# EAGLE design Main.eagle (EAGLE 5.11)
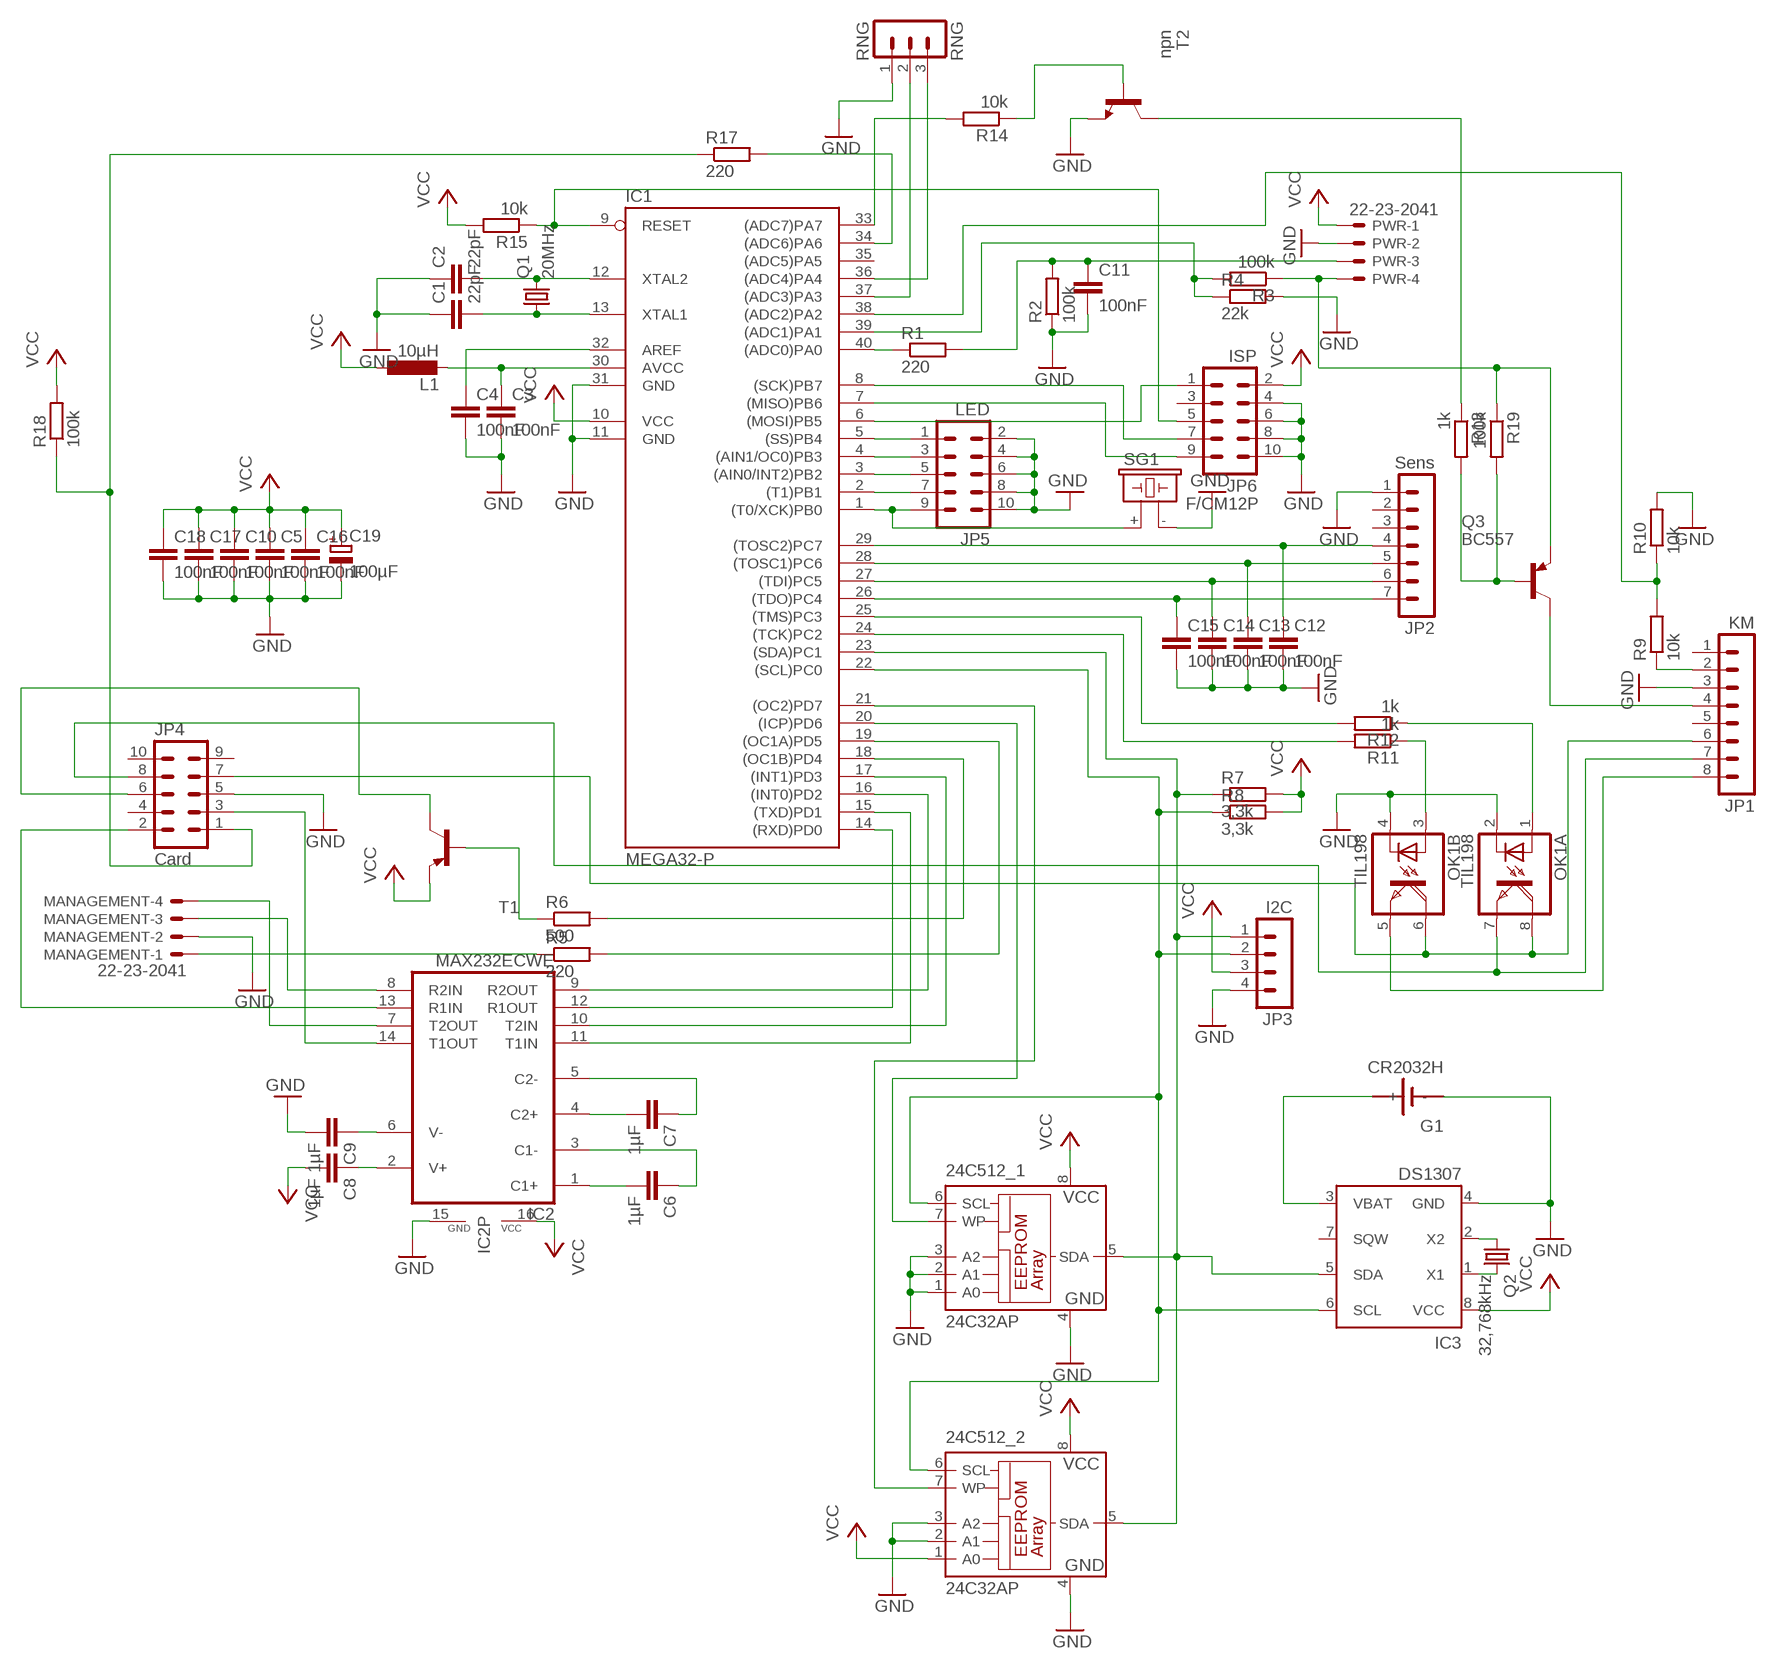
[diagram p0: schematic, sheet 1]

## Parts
24C512_1  24C32AP  [DIL8]
24C512_2  24C32AP  [DIL8]
C1  22pF  C-EUC0603  [C0603]
C2  22pF  C-EUC0603  [C0603]
C3  100nF  C-EUC0603  [C0603]
C4  100nF  C-EUC0603  [C0603]
C5  100nF  C-EUC0603  [C0603]
C6  1µF  C-EUC0603  [C0603]
C7  1µF  C-EUC0603  [C0603]
C8  1µF  C-EUC0603  [C0603]
C9  1µF  C-EUC0603  [C0603]
C10  100nF  C-EUC0603  [C0603]
C11  100nF  C-EUC0603  [C0603]
C12  100nF  C-EUC0603  [C0603]
C13  100nF  C-EUC0603  [C0603]
C14  100nF  C-EUC0603  [C0603]
C15  100nF  C-EUC0603  [C0603]
C16  100nF  C-EUC0603  [C0603]
C17  100nF  C-EUC0603  [C0603]
C18  100nF  C-EUC0603  [C0603]
C19  100µF  CPOL-EUE2.5-7  [E2,5-7]
G1  CR2032H  SN2032  [SN2032]
IC1  MEGA32-P  [DIL40]
IC2  MAX232ECWE  [SO16L]
IC3  DS1307  [DIL08]
JP1  KM  MA08-1  [MA08-1]
JP2  Sens  MA07-1  [MA07-1]
JP3  I2C  MA04-1  [MA04-1]
JP4  Card  MA05-2  [MA05-2]
JP5  LED  ML10  [ML10]
JP6  ISP  ML10  [ML10]
L1  10µH  L-EU0207/7  [0207/7]
MANAGEMENT  22-23-2041  [22-23-2041]
OK1  TIL198  [DIL08]
PWR  22-23-2041  [22-23-2041]
Q1  20MHz  CRYSTALHC49S  [HC49/S]
Q2  32,768kHz  CRYSTALTC26H  [TC26H]
Q3  BC557  [TO92-EBC]
R1  220  R-EU_R0603  [R0603]
R2  100k  R-EU_R0603  [R0603]
R3  100k  R-EU_R0603  [R0603]
R4  22k  R-EU_R0603  [R0603]
R5  220  R-EU_R0603  [R0603]
R6  500  R-EU_R0603  [R0603]
R7  3,3k  R-EU_R0603  [R0603]
R8  3,3k  R-EU_R0603  [R0603]
R9  10k  R-EU_R0603  [R0603]
R10  10k  R-EU_R0603  [R0603]
R11  1k  R-EU_R0603  [R0603]
R12  1k  R-EU_R0603  [R0603]
R13  1k  R-EU_R0603  [R0603]
R14  10k  R-EU_R0603  [R0603]
R15  10k  R-EU_R0603  [R0603]
R17  220  R-EU_R0603  [R0603]
R18  100k  R-EU_R0603  [R0603]
R19  100k  R-EU_R0603  [R0603]
RNG  RNG  MA03-1  [MA03-1]
SG1  F/CM12P  [F/CM12P]
T1  BC557  [TO92-EBC]
T2  npn  BC167-NPN-TO92-ECB  [TO92-ECB]

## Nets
AVCC: C3.1 IC1.30(AVCC) L1.2
GND: 24C512_1.1(A0) 24C512_1.2(A1) 24C512_1.3(A2) 24C512_1.4(GND) 24C512_2.2(A1) 24C512_2.3(A2) 24C512_2.4(GND) C1.1 C2.1 C3.2 C4.2 C5.2 C9.2 C10.2 C11.2 C12.2 C13.2 C14.2 C15.2 C16.2 C17.2 C18.2 C19.- G1.- IC1.11(GND) IC1.31(GND) IC2.15(GND) IC3.4(GND) JP1.3 JP2.1 JP3.4 JP4.5 JP5.2 JP5.4 JP5.6 JP5.8 JP5.10 JP6.4 JP6.6 JP6.8 JP6.10 MANAGEMENT.2 OK1.2(A:C) OK1.4(B:C) PWR.2 R2.1 R4.2 R10.2 RNG.1 SG1.- T2.E
N$2: C4.1 IC1.32(AREF)
N$3: IC1.8((SCK)PB7) JP6.7
N$4: IC1.7((MISO)PB6) JP6.9
N$5: C6.2 IC2.1(C1+)
N$6: C6.1 IC2.3(C1-)
N$7: C1.2 IC1.13(XTAL1) Q1.1
N$8: C2.2 IC1.12(XTAL2) Q1.2
N$9: C7.2 IC2.4(C2+)
N$10: C7.1 IC2.5(C2-)
N$11: C9.1 IC2.6(V-)
N$12: C8.1 IC2.2(V+)
N$13: IC1.6((MOSI)PB5) JP6.1
N$14: IC1.9(RESET) JP6.5 R15.1
N$15: IC1.14((RXD)PD0) IC2.12(R1OUT)
N$16: IC1.15((TXD)PD1) IC2.11(T1IN)
N$17: IC1.16((INT0)PD2) IC2.9(R2OUT)
N$18: IC1.17((INT1)PD3) IC2.10(T2IN)
N$19: IC1.1((T0/XCK)PB0) JP5.9 SG1.+
N$20: IC1.2((T1)PB1) JP5.7
N$21: IC1.3((AIN0/INT2)PB2) JP5.5
N$22: IC1.4((AIN1/OC0)PB3) JP5.3
N$23: IC1.5((SS)PB4) JP5.1
N$25: IC2.7(T2OUT) MANAGEMENT.4
N$26: C11.1 PWR.3 R1.2 R2.2
N$27: IC1.40((ADC0)PA0) R1.1
N$28: C12.1 IC1.29((TOSC2)PC7) JP2.4
N$29: IC1.39((ADC1)PA1) R3.2 R4.1
N$30: C13.1 IC1.28((TOSC1)PC6) JP2.5
N$31: C14.1 IC1.27((TDI)PC5) JP2.6
N$32: C15.1 IC1.26((TDO)PC4) JP2.7
N$33: IC2.8(R2IN) MANAGEMENT.3
N$34: R6.1 T1.B
N$35: IC1.19((OC1A)PD5) R5.2
N$36: MANAGEMENT.1 R5.1
N$37: IC1.18((OC1B)PD4) R6.2
N$38: IC2.13(R1IN) JP4.2
N$39: IC2.14(T1OUT) JP4.3
N$40: JP1.6 JP4.7 OK1.6(B:COL) OK1.8(A:COL)
N$41: IC1.34((ADC6)PA6) R17.2
N$42: JP4.6 T1.C
N$43: IC3.2(X2) Q2.1
N$44: IC3.1(X1) Q2.2
N$45: 24C512_1.5(SDA) 24C512_2.5(SDA) IC1.23((SDA)PC1) IC3.5(SDA) JP3.1 R7.1
N$46: IC1.25((TMS)PC3) R12.2
N$47: OK1.3(B:A) R11.1
N$48: OK1.1(A:A) R12.1
N$49: 24C512_1.6(SCL) 24C512_2.6(SCL) IC1.22((SCL)PC0) IC3.6(SCL) JP3.2 R8.1
N$50: 24C512_1.7(WP) IC1.20((ICP)PD6)
N$51: 24C512_2.7(WP) IC1.21((OC2)PD7)
N$52: JP4.1 R17.1 R18.1
N$53: G1.+ IC3.3(VBAT)
N$54: JP1.7 JP4.8 OK1.7(A:EMI)
N$55: JP1.8 OK1.5(B:EMI)
N$56: JP1.4 Q3.C
N$57: IC1.38((ADC2)PA2) R9.2 R10.1
N$58: R13.1 T2.C
N$59: JP1.2 R9.1
N$60: Q3.B R13.2 R19.2
N$61: IC1.24((TCK)PC2) R11.2
N$62: IC1.33((ADC7)PA7) R14.2
N$63: R14.1 T2.B
N$64: PWR.4 Q3.E R3.1 R19.1
N$65: IC1.37((ADC3)PA3) RNG.2
N$66: IC1.36((ADC4)PA4) RNG.3
VCC: 24C512_1.8(VCC) 24C512_2.1(A0) 24C512_2.8(VCC) C5.1 C8.2 C10.1 C16.1 C17.1 C18.1 C19.+ IC1.10(VCC) IC2.16(VCC) IC3.8(VCC) JP3.3 JP6.2 L1.1 PWR.1 R7.2 R8.2 R15.2 R18.2 T1.E
Unconnected: IC1.35((ADC5)PA5) IC3.7(SQW) JP1.1 JP1.5 JP2.2 JP2.3 JP4.4 JP4.9 JP4.10 JP6.3

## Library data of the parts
24C512_1 24C512_2 = microchip:24*: Serial EEPROM I2C; MPN: AT24C32C-PU; OC_FARNELL: 1362652; OC_NEWARK: 50M3325
C1-C18 = rcl:C-EU: CAPACITOR, European symbol
C19 = rcl:CPOL-EU: POLARIZED CAPACITOR, European symbol
G1 = sn2032:SN2032: LI BATTERY
IC1 = atmel:MEGA32-P: MICROCONTROLLER 32 Kbytes FLASH 2 Kbytes SRAM 1 Kbytes EEPROM USART 8-channel 10 bit ADC Source: www.atmel.com .. doc2503.pdf; MPN: ATMEGA32-16PU; OC_FARNELL: 1661729; OC_NEWARK: 51P1794
IC2 = maxim:MAX232ECWE: RS232 TRANSEIVER; MF: MAXIM; MPN: MAX232ECWE+; OC_FARNELL: 9724435; OC_NEWARK: 67K4440
IC3 = ds1307_pcf8583:DS1307: I2C-Bus CLOCK/CALENDAR
JP1 = con-lstb:MA08-1: PIN HEADER; OC_FARNELL: unknown; OC_NEWARK: unknown
JP2 = con-lstb:MA07-1: PIN HEADER; OC_FARNELL: unknown; OC_NEWARK: unknown
JP3 = con-lstb:MA04-1: PIN HEADER; OC_FARNELL: unknown; OC_NEWARK: unknown
JP4 = con-lstb:MA05-2: PIN HEADER; OC_FARNELL: unknown; OC_NEWARK: unknown
JP5 JP6 = con-ml:ML10: HARTING; OC_FARNELL: unknown; OC_NEWARK: unknown
L1 = rcl:L-EU: INDUCTOR, European symbol
MANAGEMENT PWR = con-molex:22-23-2041: .100" (2.54mm) Center Header - 4 Pin; MF: MOLEX; MPN: 22-23-2041; OC_FARNELL: 1462920; OC_NEWARK: 38C0355
OK1 = optocoupler:TIL198: TEXAS INSTRUMENTS OPTO COUPLER; OC_FARNELL: unknown; OC_NEWARK: unknown
Q1 = crystal:CRYSTAL: CRYSTAL; OC_FARNELL: 1667008; OC_NEWARK: unknown
Q2 = crystal:CRYSTAL: CRYSTAL; OC_FARNELL: unknown; OC_NEWARK: unknown
Q3 T1 = transistor-pnp:BC557*: PNP Transistror
R1-R15 R17-R19 = rcl:R-EU_: RESISTOR, European symbol
RNG = con-lstb:MA03-1: PIN HEADER; OC_FARNELL: unknown; OC_NEWARK: unknown
SG1 = buzzer:F/CM12P: BUZZER; OC_FARNELL: unknown; OC_NEWARK: unknown
T2 = transistor:*-NPN-: NPN Transistror BF959 corrected 2008.03.06

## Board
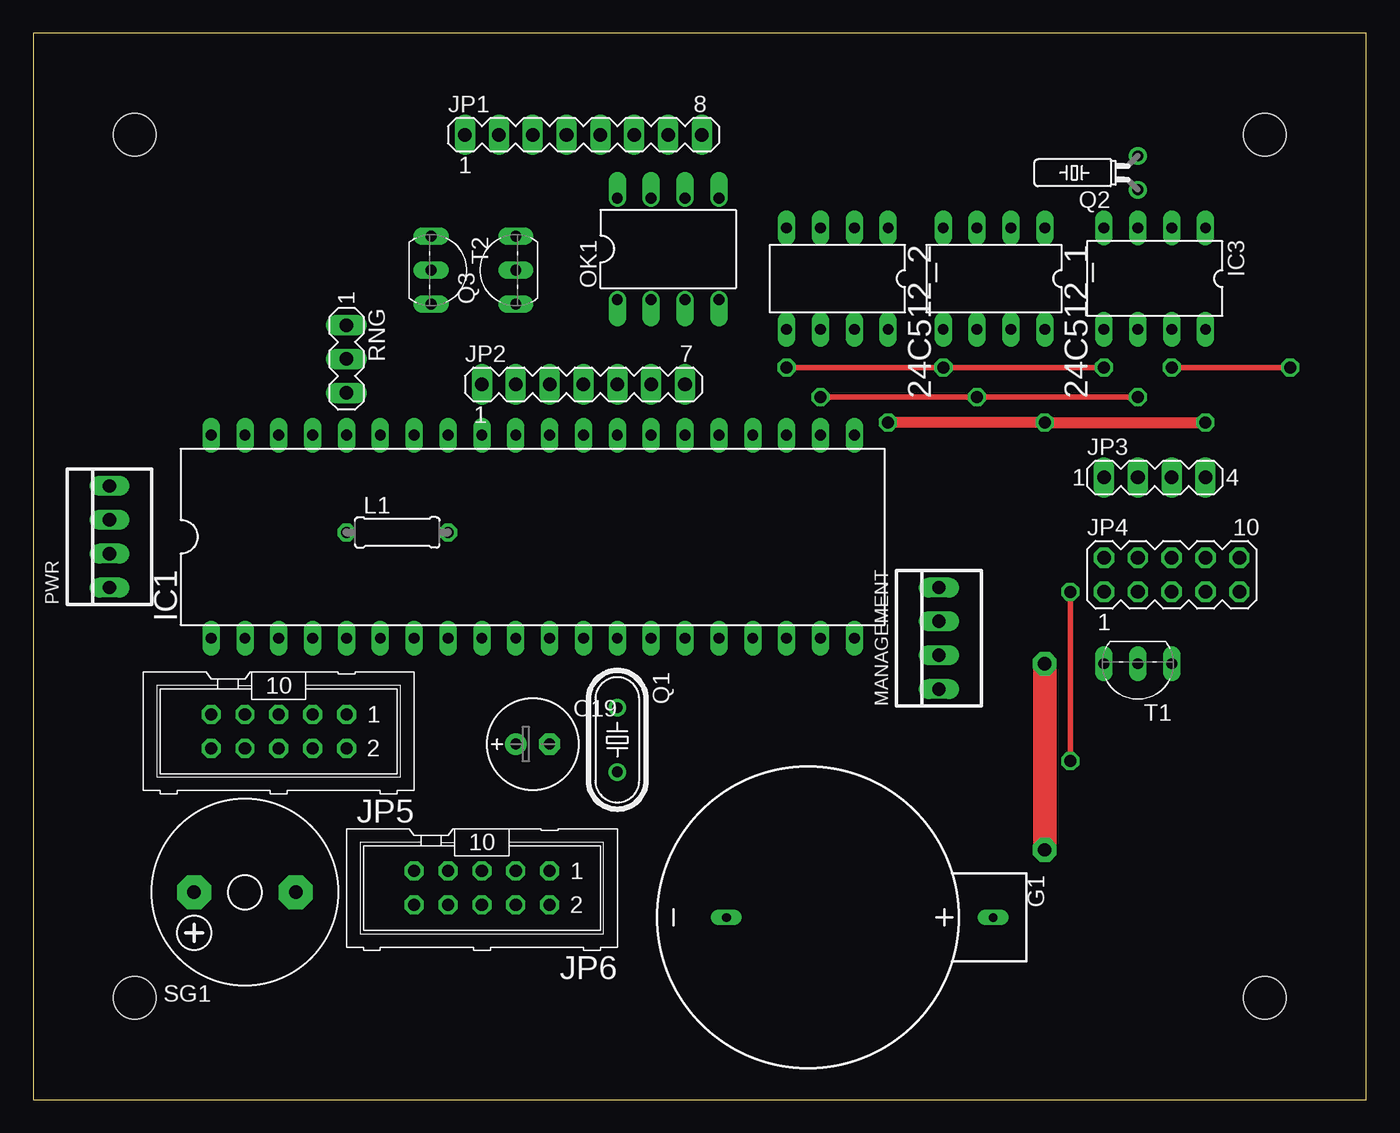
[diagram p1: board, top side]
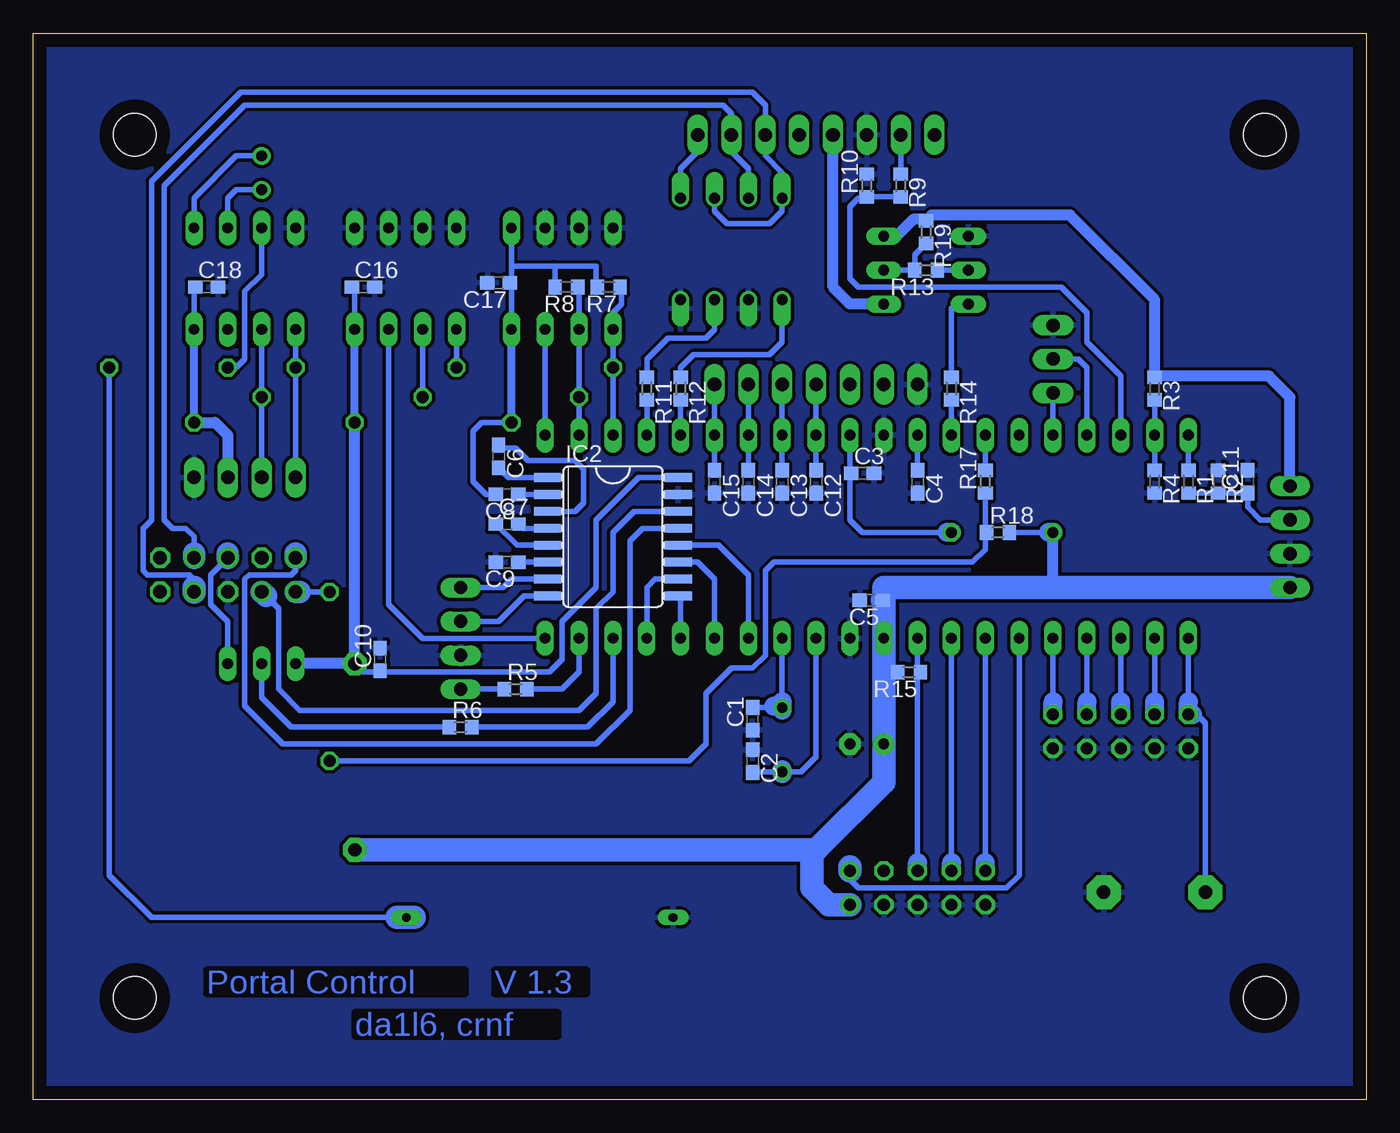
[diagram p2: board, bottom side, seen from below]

Size 100 x 80 mm. Coordinates in mm from the lower left corner, seen from the top.
Outline: 0,0 100,0 100,80 0,80 0,0
Copper layers (1*16): Top 0.035mm / dielectric 1.5mm / Bottom 0.035mm
Design rules "Bilex DRU": minimum track width 10mil, minimum drill 24mil, track to track 10mil, track to pad 10mil, pad to pad 10mil, via to via 10mil, smd to smd 10mil, copper to edge 40mil, drill to drill 8mil, minimum pad ring 10mil, minimum via ring 8mil, stop-mask expansion 4mil, vias tented up to drill 0mil, thermal gap 10mil
Holes 3.2 mm at 92.39,7.62 7.62,7.62 7.62,72.39 92.39,72.39

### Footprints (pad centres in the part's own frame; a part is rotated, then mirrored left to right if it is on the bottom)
DIL8 = drill 0.813 long: 1 -3.81,-3.81; 2 -1.27,-3.81; 3 1.27,-3.81; 4 3.81,-3.81; 5 3.81,3.81; 6 1.27,3.81; 7 -1.27,3.81; 8 -3.81,3.81
C0603 = smd 1.1 x 1: 1 -0.85,0; 2 0.85,0
E2,5-7 = drill 0.813 pad 1.6 round: + -1.27,0 | drill 0.813 pad 1.6 octagon: - 1.27,0
SN2032 = drill 0.65 long: + 0,13.9; - 0,-6.1
DIL40 = drill 0.813 long: 1 -24.13,-7.62; 2 -21.59,-7.62; 3 -19.05,-7.62; 4 -16.51,-7.62; 5 -13.97,-7.62; 6 -11.43,-7.62; 7 -8.89,-7.62; 8 -6.35,-7.62; 9 -3.81,-7.62; 10 -1.27,-7.62; 11 1.27,-7.62; 12 3.81,-7.62; 13 6.35,-7.62; 14 8.89,-7.62; 15 11.43,-7.62; 16 13.97,-7.62; 17 16.51,-7.62; 18 19.05,-7.62; 19 21.59,-7.62; 20 24.13,-7.62; 21 24.13,7.62; 22 21.59,7.62; 23 19.05,7.62; 24 16.51,7.62; 25 13.97,7.62; 26 11.43,7.62; 27 8.89,7.62; 28 6.35,7.62; 29 3.81,7.62; 30 1.27,7.62; 31 -1.27,7.62; 32 -3.81,7.62; 33 -6.35,7.62; 34 -8.89,7.62; 35 -11.43,7.62; 36 -13.97,7.62; 37 -16.51,7.62; 38 -19.05,7.62; 39 -21.59,7.62; 40 -24.13,7.62
SO16L = smd 0.66 x 2.032: 1 -4.445,-4.902; 2 -3.175,-4.902; 3 -1.905,-4.902; 4 -0.635,-4.902; 5 0.635,-4.902; 6 1.905,-4.902; 7 3.175,-4.902; 8 4.445,-4.902; 9 4.445,4.902; 10 3.175,4.902; 11 1.905,4.902; 12 0.635,4.902; 13 -0.635,4.902; 14 -1.905,4.902; 15 -3.175,4.902; 16 -4.445,4.902
DIL08 = drill 0.813 long: 1 -3.81,-3.81; 2 -1.27,-3.81; 3 1.27,-3.81; 4 3.81,-3.81; 5 3.81,3.81; 6 1.27,3.81; 7 -1.27,3.81; 8 -3.81,3.81
MA08-1 = drill 1.016 long: 1 -8.89,0; 2 -6.35,0; 3 -3.81,0; 4 -1.27,0; 5 1.27,0; 6 3.81,0; 7 6.35,0; 8 8.89,0
MA07-1 = drill 1.016 long: 1 -7.62,0; 2 -5.08,0; 3 -2.54,0; 4 0,0; 5 2.54,0; 6 5.08,0; 7 7.62,0
MA04-1 = drill 1.016 long: 1 -3.81,0; 2 -1.27,0; 3 1.27,0; 4 3.81,0
MA05-2 = drill 1.016 octagon: 1 -5.08,-1.27; 2 -5.08,1.27; 3 -2.54,-1.27; 4 -2.54,1.27; 5 0,-1.27; 6 0,1.27; 7 2.54,-1.27; 8 2.54,1.27; 9 5.08,-1.27; 10 5.08,1.27
ML10 = drill 0.914 octagon: 1 -5.08,-1.27; 2 -5.08,1.27; 3 -2.54,-1.27; 4 -2.54,1.27; 5 0,-1.27; 6 0,1.27; 7 2.54,-1.27; 8 2.54,1.27; 9 5.08,-1.27; 10 5.08,1.27
0207/7 = drill 0.813 octagon: 1 -3.81,0; 2 3.81,0
22-23-2041 = drill 1 long: 1 -3.81,0; 2 -1.27,0; 3 1.27,0; 4 3.81,0
DIL08' = drill 0.813 offset: 1 -3.81,-3.81; 2 -1.27,-3.81; 3 1.27,-3.81; 4 3.81,-3.81; 5 3.81,3.81; 6 1.27,3.81; 7 -1.27,3.81; 8 -3.81,3.81
HC49/S = drill 0.813 round: 1 -2.413,0; 2 2.413,0
TC26H = drill 0.813 round: 1 -1.27,0; 2 1.27,0
TO92-EBC = drill 0.813 long: B 0,-1.27; C -2.54,-1.27; E 2.54,-1.27
R0603 = smd 1 x 1.1: 1 -0.85,0; 2 0.85,0
MA03-1 = drill 1.016 long: 1 -2.54,0; 2 0,0; 3 2.54,0
F/CM12P = drill 1.016 pad 2.54 octagon: + 3.81,0; - -3.81,0
TO92-ECB = drill 0.813 long: B 2.54,0; C 0,0; E -2.54,0

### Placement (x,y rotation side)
24C512_1  72.07,61.59 180 top
24C512_2  60.33,61.59 180 top
C1  46.04,28.57 90 bottom
C2  46.04,25.4 270 bottom
C3  37.78,46.99 0 bottom
C4  33.66,46.35 270 bottom
C5  37.15,37.47 180 bottom
C6  65.09,48.26 270 bottom
C7  64.45,43.18 0 bottom
C8  64.45,45.4 180 bottom
C9  64.45,40.32 180 bottom
C10  73.98,33.02 90 bottom
C11  8.89,46.35 90 bottom
C12  41.27,46.35 270 bottom
C13  43.81,46.35 270 bottom
C14  46.35,46.35 270 bottom
C15  48.9,46.35 270 bottom
C16  75.25,60.96 0 bottom
C17  65.09,61.28 180 bottom
C18  87,60.96 0 bottom
C19  37.47,26.67 0 top
G1  58.1,13.65 270 top
IC1  37.47,42.23 0 top
IC2  56.52,42.23 270 bottom
IC3  84.14,61.59 180 top
JP1  41.27,72.39 0 top
JP2  41.27,53.66 0 top
JP3  84.14,46.67 0 top
JP4  85.41,39.37 0 top
JP5  18.41,27.62 180 top
JP6  33.66,15.88 180 top
L1  27.3,42.55 0 top
MANAGEMENT  67.94,34.61 90 top
OK1  TIL198  [DIL08']  47.62,63.82 0 top
PWR  5.71,42.23 90 top
Q1  43.81,26.99 270 top
Q2  82.87,69.53 90 top
Q3  34.92,62.23 90 top
R1  13.34,46.35 270 bottom
R2  11.11,46.35 270 bottom
R3  15.88,53.34 270 bottom
R4  15.88,46.35 270 bottom
R5  63.82,30.8 0 bottom
R6  67.94,27.94 0 bottom
R7  56.83,60.96 180 bottom
R8  60.01,60.96 180 bottom
R9  34.92,68.58 270 bottom
R10  37.47,68.58 90 bottom
R11  53.98,53.34 270 bottom
R12  51.44,53.34 270 bottom
R13  33.02,62.23 180 bottom
R14  31.11,53.34 270 bottom
R15  34.29,32.07 180 bottom
R17  28.57,46.35 90 bottom
R18  27.62,42.55 0 bottom
R19  33.02,65.09 270 bottom
RNG  23.5,55.56 270 top
SG1  15.88,15.56 180 top
T1  82.87,31.43 180 top
T2  29.84,62.23 270 top

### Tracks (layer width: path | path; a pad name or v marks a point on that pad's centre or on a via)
AVCC
  Bottom 0.406: IC1.30 38.73,47.09 C3.1 38.73,46.89 38.73,43.5 37.78,42.55 31.43,42.55
  Bottom 1.422: L1.2 31.43,42.55
GND
  pour Bottom: 0,0 0,80.01 100.01,80.01 100.01,78.42 100.01,0
N$1
  Bottom 1.422: 43.81,24.45 43.81,24.77
N$2
  Bottom 0.406: C4.1 IC1.32
N$3
  Bottom 0.406: 31.11,17.78 IC1.8
  Bottom 1.422: JP6.7 31.11,17.78
N$4
  Bottom 0.406: 28.57,17.78 IC1.7
  Bottom 1.422: JP6.9 28.57,17.78
N$5
  Bottom 0.406: IC2.1 64.35,46.67 C6.2
N$6
  Bottom 0.406: IC2.3 59.37,44.13 58.74,44.77 58.74,47.31 59.37,47.94 62.87,47.94 63.82,48.9 64.87,48.9 C6.1
N$7
  Bottom 0.406: C1.2 46.01,29.4 Q1.1 43.81,29.53 | 43.81,29.84 IC1.13
  Bottom 1.422: 43.81,29.53 43.81,29.84 | 43.81,29.53 43.81,29.21 | 43.81,29.53 44.45,29.53
N$8
  Bottom 0.406: C2.2 46.01,24.57 Q1.2 42.42,24.57 41.27,25.72 IC1.12
N$9
  Bottom 0.406: IC2.4 63.28,42.86 C7.2
N$10
  Bottom 0.406: IC2.5 63.72,41.59 C7.1
N$11
  Bottom 0.406: IC2.6 C9.1
N$12
  Bottom 0.406: IC2.2 C8.1
N$13
  Bottom 0.406: IC1.6 26.04,16.83 26.99,15.88 38.1,15.88 38.73,16.51 JP6.1
  Bottom 1.778: JP6.1 38.73,17.46
N$14
  Bottom 0.406: 33.66,31.85 IC1.9 | 33.66,31.85 R15.1 | 33.66,17.78 33.66,31.85
  Bottom 1.422: JP6.5 33.66,17.78
N$15
  Bottom 0.406: IC1.14 46.35,39.37 48.58,41.59 IC2.12
N$16
  Bottom 0.406: IC1.15 48.9,39.05 50.16,40.32 IC2.11
N$17
  Bottom 0.406: IC1.16 51.44,37.64 IC2.9
N$18
  Bottom 0.406: IC2.10 53.34,39.05 53.98,38.42 IC1.17
N$19
  Bottom 0.406: 13.34,33.34 IC1.1 13.34,29.84 | SG1.+ 12.06,28.26 12.7,28.89 13.02,28.89
  Bottom 1.422: 13.34,29.84 JP5.9 13.02,28.89
N$20
  Bottom 0.406: 15.88,29.84 IC1.2
  Bottom 1.422: JP5.7 15.88,29.84
N$21
  Bottom 0.406: 18.41,33.34 IC1.3 18.41,29.84
  Bottom 1.422: JP5.5 18.41,29.84
N$22
  Bottom 0.406: 20.95,29.84 IC1.4
  Bottom 1.422: JP5.3 20.95,29.84
N$23
  Bottom 0.406: 23.5,29.84 IC1.5
  Bottom 1.422: JP5.1 23.5,29.84
N$25
  Bottom 0.406: IC2.7 64.14,39.05 64.77,38.42 MANAGEMENT.4
N$26
  Bottom 0.406: PWR.3 7.94,43.5 8.89,44.45 C11.1 R2.2 R1.2
N$27
  Bottom 0.406: R1.1 IC1.40
N$28
  Bottom 0.406: JP2.4 IC1.29 C12.1
N$29
  Bottom 0.406: R4.1 IC1.39 R3.2
N$30
  Bottom 0.406: C13.1 IC1.28 JP2.5
N$31
  Bottom 0.406: JP2.6 IC1.27 C14.1
N$32
  Bottom 0.406: C15.1 IC1.26 JP2.7
N$33
  Bottom 0.406: IC2.8 63.18,37.78 65.09,35.88 MANAGEMENT.3
N$34
  Bottom 0.406: R6.1 80.64,27.94 82.87,30.16 T1.B
N$35
  Bottom 0.406: R5.2 60.33,30.8 59.05,32.07 IC1.19
N$36
  Bottom 0.406: R5.1 MANAGEMENT.1
N$37
  Bottom 0.406: IC1.18 56.52,29.84 58.42,27.94 R6.2
N$38
  Bottom 0.406: IC2.13 54.29,42.86 55.24,41.91 55.24,29.21 57.78,26.67 81.28,26.67 84.14,29.53 84.14,39.05 83.82,39.37 80.64,39.37 80.33,39.69 JP4.2
  Bottom 1.676: JP4.2 80.33,40.96
N$39
  Bottom 0.406: IC2.14 54.93,44.13 56.52,42.55 56.52,38.1 57.78,36.83 57.78,30.48 59.05,29.21 80.01,29.21 81.6,30.8 81.6,36.83 82.55,37.78
  Bottom 1.676: 82.55,37.78 JP4.3
N$40
  Bottom 0.406: OK1.6 48.9,66.67 47.94,65.72 44.77,65.72 43.81,66.67 OK1.8 43.81,69.53 45.09,70.8 JP1.6 45.09,74.61 46.04,75.56 84.45,75.56 91.12,68.9 91.12,43.5 91.76,42.86 91.76,39.69 91.44,39.37 88.27,39.37 | 88.27,39.37 87.95,39.05 | 87.95,38.42 88.27,38.42 88.27,39.37
  Bottom 1.778: 87.95,38.42 JP4.7
N$41
  Bottom 0.406: R17.2 IC1.34
N$42
  Bottom 0.406: T1.C 85.41,35.88 86.68,37.15 86.68,39.37 JP4.6
  Bottom 1.676: JP4.6 85.41,40.96
N$43
  Bottom 0.406: IC3.2 85.41,67.63 84.77,68.26 Q2.1
N$44
  Bottom 0.406: IC3.1 87.95,67.63 84.77,70.8 Q2.2
N$45  (via drill 0.9)
  Top 0.406: v56.52,54.93 v68.26,54.93 v80.33,54.93
  Bottom 0.406: IC1.23 v56.52,54.93 24C512_2.5 56.52,59.05 55.88,59.69 55.88,60.86 R7.1 | v68.26,54.93 24C512_1.5 | IC3.5 v80.33,54.93 JP3.1
N$46
  Bottom 0.406: IC1.25 R12.2
N$47
  Bottom 0.406: R11.1 53.98,55.56 52.39,57.15 49.53,57.15 48.9,57.78 OK1.3
N$48
  Bottom 0.406: R12.1 51.44,54.93 50.48,55.88 44.77,55.88 43.81,56.83 OK1.1
N$49  (via drill 0.9)
  Top 0.406: v59.05,52.7 v70.8,52.7 v82.87,52.7
  Bottom 0.406: IC1.22 v59.05,52.7 24C512_2.6 59.05,60.86 R8.1 | v70.8,52.7 24C512_1.6 | IC3.6 v82.87,52.7 JP3.2
N$50
  Bottom 0.406: IC1.20 70.8,34.61 73.34,37.15 24C512_1.7
N$51
  Bottom 0.406: IC1.21 24C512_2.7
N$52  (via drill 0.9 pad 1.27)
  Top 0.406: v77.79,25.4 v77.79,38.1
  Bottom 0.406: v77.79,38.1 80.01,38.1 | v77.79,25.4 50.8,25.4 49.53,26.67 49.53,30.48 47.62,32.38 46.04,32.38 45.09,33.34 45.09,39.69 44.45,40.32 29.53,40.32 28.57,41.27 28.57,42.44 R18.1 28.57,42.65 R17.1
  Bottom 1.676: 80.01,38.1 JP4.1
N$53  (via drill 0.9 pad 1.27)
  Top 0.406: v94.3,54.93 v85.41,54.93
  Bottom 0.406: IC3.3 82.87,61.91 84.14,60.64 84.14,55.56 84.77,54.93 v85.41,54.93 | v94.3,54.93 94.3,16.83 91.12,13.65 72.71,13.65 | G1.+ 72.07,13.65
  Bottom 1.778: 72.71,13.65 72.07,13.65 71.44,13.65
N$54
  Bottom 0.406: OK1.7 46.35,69.85 47.62,71.12 JP1.7 47.62,73.98 48.26,74.61 84.14,74.61 90.17,68.58 90.17,43.5 89.53,42.86 88.58,42.86 87.95,42.23 87.95,40.96
  Bottom 1.676: 87.95,40.96 JP4.8
N$55
  Bottom 0.406: JP1.8 50.16,71.12 51.44,69.85 OK1.5
N$56
  Bottom 0.813: JP1.4 40.01,60.96 38.73,59.69 Q3.C
N$57
  Bottom 0.406: 34.82,67.63 R9.2 R10.1 37.57,67.63 38.1,67.63 38.73,66.99 38.73,61.59 38.1,60.96 22.86,60.96 20.95,59.05 20.95,56.83 18.41,54.29 IC1.38
N$58
  Bottom 0.406: T2.C R13.1
N$59
  Bottom 0.406: R9.1 JP1.2
N$60
  Bottom 0.406: Q3.B R13.2 33.87,63.39 R19.2
N$61
  Bottom 0.406: IC1.24 R11.2
N$62
  Bottom 0.406: IC1.33 R14.2
N$63
  Bottom 0.406: R14.1 31.11,59.37 30.8,59.69 T2.B
N$64
  Bottom 0.813: PWR.4 5.71,52.7 7.3,54.29 15.77,54.29 R3.1 15.88,60.01 22.23,66.36 32.6,66.36 R19.1 33.12,66.04 33.97,66.04 35.24,64.77 Q3.E
N$65
  Bottom 0.406: IC1.37 20.95,54.93 21.59,55.56 RNG.2
N$66
  Bottom 0.406: IC1.36 RNG.3
VCC  (via drill 0.9, 1 pad 1.78)
  Top 0.406: v75.88,50.8 76.2,50.8
  Top 0.813: v64.14,50.8 v75.88,50.8 v87.95,50.8
  Top 1.778: v75.88,18.73 v75.88,32.7
  Bottom 0.406: 24C512_1.8 75.88,60.74 C16.1 75.88,61.17 | 64.14,62.55 24C512_2.1 | IC3.8 87.95,60.86 C18.1 | v64.14,50.8 66.36,50.8 66.99,50.16 66.99,46.35 66.04,45.4 C8.2 | 64.14,62.55 60.96,62.55 | R8.2 60.86,62.45 60.96,62.55 | 60.96,62.55 57.78,62.55 57.78,60.96 R7.2 | 64.14,62.55 64.14,61.38 C17.1 64.14,60.86 24C512_2.8 | 74.3,32.07 61.28,32.07 60.33,33.02 60.33,35.88 57.78,38.42 57.78,43.5 54.61,46.67 IC2.16 | C10.1 74.19,32.17 74.3,32.07 | 36.2,32.07 R15.2 | 74.3,32.07 75.25,32.07 v75.88,32.7 | 23.81,42.55 R18.2
  Bottom 0.61: v75.88,50.8 24C512_1.8 | v64.14,50.8 24C512_2.8 | v87.95,50.8 IC3.8
  Bottom 0.813: v87.95,50.8 86.36,50.8 85.41,49.85 JP3.3 | v75.88,50.8 v75.88,32.7 T1.E | 23.5,38.42 L1.1
  Bottom 1.422: L1.1 23.81,42.55
  Bottom 1.778: 36.2,37.47 IC1.10 36.2,32.07 C19.+ 36.2,23.81 41.12,18.89 41.27,18.73 | 36.2,37.47 C5.1 | 36.2,37.47 36.2,38.42 23.5,38.42 PWR.1 | JP6.2 40.32,14.61 41.59,15.88 41.59,18.41 41.27,18.73 | 41.27,18.73 v75.88,18.73

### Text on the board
Bottom: V 1.3 | Portal Control | da1l6, crnf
